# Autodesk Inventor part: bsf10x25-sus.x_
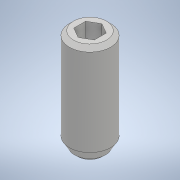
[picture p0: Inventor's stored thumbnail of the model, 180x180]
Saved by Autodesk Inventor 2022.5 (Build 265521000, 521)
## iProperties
Created: 2020-01
Part Number: bsf10x25-sus.x_
Material: 一般
Document SubType Name: Modeling
Designer: ImaoCorp
Density: 1 g/cm^3
Appearance: 既定
Sending System: SOLIDWORKS 2018-2018316
MC: AMD64
MC_MODEL: Intel64 Family 6 Model 60 Stepping 3, GenuineIntel
OS: Windows_NT
FRU: Parasolid Version 30.0, build 310,  6- 8-2018
FORMAT: text
GUISE: transmit
KEY: bsf10x25-sus
FILE: bsf10x25-sus.x_t
DATE: Thu Jan 23 16:49:18 2020
Author: ImaoCorp
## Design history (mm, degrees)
feature "Base1"
node "ソリッド1"
